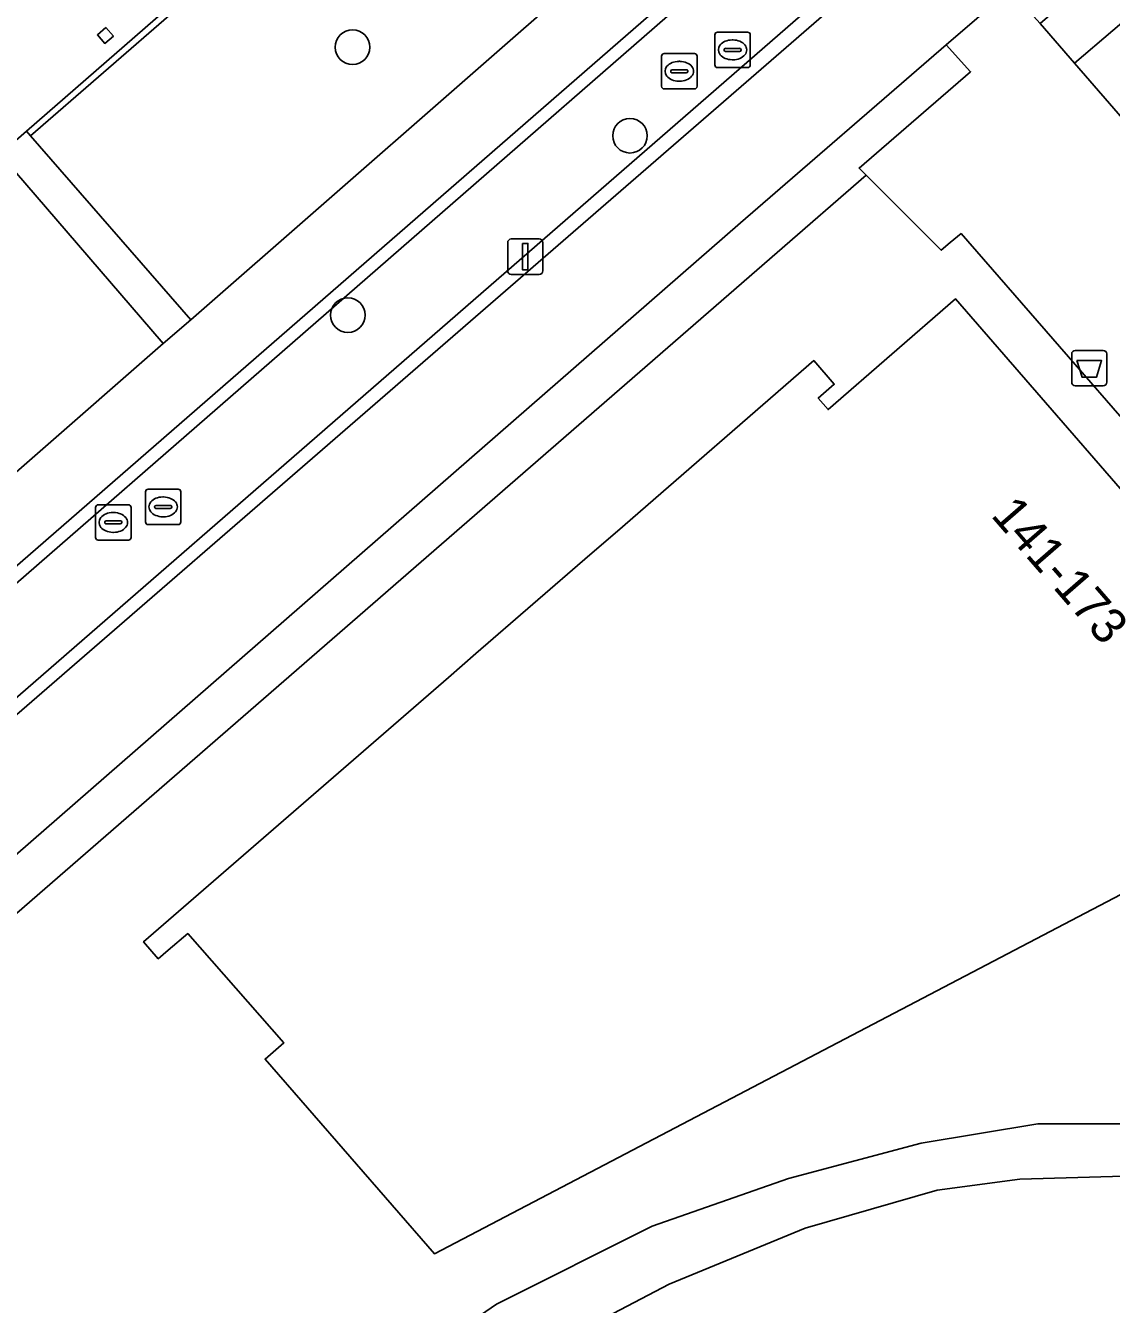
# Model space of a CAD drawing. Extents: x 155887 to 156869, y 383880 to 384678.
# Drawn here: x 156245.28 to 156275.97, y 384049.47 to 384085.6 of the extents above; entities that cross this region are included whole.
import ezdxf

# ---------------------------------------------------------------- set-up
doc = ezdxf.new("R2010")
doc.units = 0
for name, color, linetype in [('IMGEO_Afvalbak', 7, 'Continuous'), ('IMGEO_Berm_groen', 7, 'Continuous'), ('IMGEO_Boom', 7, 'Continuous'), ('IMGEO_Erf', 7, 'Continuous'), ('IMGEO_Fietspad_gesloten', 7, 'Continuous'), ('IMGEO_Greppel_droge_sloot', 7, 'Continuous'), ('IMGEO_Groenvoorziening', 7, 'Continuous'), ('IMGEO_Haag', 7, 'Continuous'), ('IMGEO_Kolk', 7, 'Continuous'), ('IMGEO_Lichtmast', 7, 'Continuous'), ('IMGEO_Pand', 7, 'Continuous'), ('IMGEO_Pand_nummerreeks', 7, 'Continuous'), ('IMGEO_Voetpad_gesloten', 7, 'Continuous'), ('IMGEO_Voetpad_open', 7, 'Continuous')]:
    doc.layers.add(name, color=color, linetype=linetype)

msp = doc.modelspace()

# ---------------------------------------------------------------- linework, layer by layer
at = {"layer": 'IMGEO_Afvalbak'}
for p, q in [((156274.942, 384076.424), (156275.732, 384076.424)), ((156275.732, 384076.424), (156274.942, 384076.424)), ((156274.842, 384075.524), (156274.842, 384076.324)), ((156274.842, 384076.324), (156274.842, 384075.524)), ((156275.832, 384076.324), (156275.832, 384075.524)), ((156275.832, 384075.524), (156275.832, 384076.324)), ((156275.732, 384075.424), (156274.942, 384075.424)), ((156274.942, 384075.424), (156275.732, 384075.424))]:
    msp.add_line(p, q, dxfattribs=at)
msp.add_lwpolyline([(156274.985, 384076.138), (156275.689, 384076.138), (156275.54, 384075.668), (156275.134, 384075.668), (156274.985, 384076.138)], dxfattribs=at)
for centre, start, end in [((156274.942, 384076.324), 90, 180), ((156274.942, 384076.324), 90, 180), ((156275.732, 384076.324), 0, 90), ((156275.732, 384076.324), 360, 90), ((156274.942, 384075.524), 180, 270), ((156274.942, 384075.524), 180, 270), ((156275.732, 384075.524), 270, 0), ((156275.732, 384075.524), 270, 0)]:
    msp.add_arc(centre, 0.1, start, end, dxfattribs=at)
at = {"layer": 'IMGEO_Berm_groen'}
for points in [[(156267.782, 384090.109), (156262.74, 384085.745), (156228.231, 384055.73), (156230.294, 384053.373), (156269.896, 384087.691)], [(156277.086, 384086.398), (156274.92, 384084.542), (156304.211, 384050.794), (156306.425, 384052.676)]]:
    msp.add_lwpolyline(points, close=True, dxfattribs=at)
for points in [[(156229.652, 384056.467), (156266.709, 384088.74)], [(156268.552, 384087.083), (156231.611, 384054.962)]]:
    msp.add_lwpolyline(points, dxfattribs=at)
at = {"layer": 'IMGEO_Boom'}
for centre in [(156254.52, 384084.99), (156262.36, 384082.49), (156254.388, 384077.422)]:
    msp.add_circle(centre, 0.489, dxfattribs=at)
at = {"layer": 'IMGEO_Erf'}
for points in [[(156233.788, 384073.174), (156236.052, 384075.143), (156235.843, 384075.385), (156236.084, 384075.595), (156236.293, 384075.353), (156236.363, 384075.42), (156236.657, 384075.088), (156237.409, 384075.743), (156244.556, 384081.969), (156245.305, 384082.622), (156261.783, 384096.974), (156257.057, 384102.381), (156253.783, 384106.157), (156249.606, 384110.968), (156241.618, 384120.183), (156237.428, 384125.007), (156235.411, 384127.346), (156228.952, 384134.784), (156195.288, 384105.561), (156189.338, 384100.396), (156193.713, 384095.326), (156201.684, 384086.153), (156205.864, 384081.345), (156221.93, 384062.847)], [(156247.552, 384085.548), (156247.761, 384085.306), (156247.519, 384085.096), (156247.31, 384085.338)]]:
    msp.add_lwpolyline(points, close=True, dxfattribs=at)
for points in [[(156276.904, 384073.775), (156271.716, 384079.723), (156271.41, 384079.469), (156271.154, 384079.254), (156269.034, 384081.375), (156170.141, 383995.483)], [(156278.03, 384061.999), (156256.833, 384050.902), (156252.05, 384056.404), (156252.576, 384056.861), (156249.864, 384059.949), (156249.309, 384059.476), (156249.027, 384059.236), (156248.615, 384059.719), (156257.228, 384067.188), (156258.004, 384067.858), (156261.223, 384070.65), (156262.005, 384071.319), (156267.555, 384076.135), (156268.131, 384075.47), (156267.678, 384075.077), (156267.96, 384074.752), (156271.563, 384077.878), (156276.399, 384072.304)], [(156253.789, 384046.184), (156258.588, 384049.482), (156262.988, 384051.68), (156266.837, 384053.029), (156270.587, 384054.028), (156273.886, 384054.577), (156276.336, 384054.577), (156276.642, 384054.607), (156276.789, 384053.144), (156276.326, 384053.098), (156273.378, 384053.011), (156271.04, 384052.699), (156267.307, 384051.623), (156263.463, 384050.043), (156260.322, 384048.399)]]:
    msp.add_lwpolyline(points, dxfattribs=at)
at = {"layer": 'IMGEO_Fietspad_gesloten'}
for points in [[(156321.213, 384132.469), (156314.047, 384125.913), (156291.359, 384106.231), (156284.254, 384100.056), (156283.954, 384099.797), (156269.896, 384087.691), (156230.294, 384053.373), (156228.715, 384051.972), (156223.252, 384047.246), (156221.532, 384045.745), (156182.003, 384011.384), (156180.455, 384010.006), (156174.916, 384005.204), (156173.353, 384003.808), (156169.034, 384000), (156168.573, 383999.541)], [(156225.091, 384044.821), (156232.142, 384050.972), (156265.486, 384080.026), (156271.299, 384085.055), (156273.092, 384086.615), (156283.541, 384095.347), (156286.027, 384097.441), (156286.341, 384097.706), (156304.975, 384114.033), (156305.378, 384113.591), (156305.662, 384113.279), (156306.714, 384114.217), (156306.4, 384114.594), (156306.05, 384115.013), (156315.997, 384123.54), (156323.254, 384130.15), (156323.467, 384130.447)]]:
    msp.add_lwpolyline(points, dxfattribs=at)
at = {"layer": 'IMGEO_Greppel_droge_sloot'}
for points in [[(156266.709, 384088.74), (156229.652, 384056.467)], [(156231.611, 384054.962), (156268.552, 384087.083)]]:
    msp.add_lwpolyline(points, dxfattribs=at)
at = {"layer": 'IMGEO_Groenvoorziening'}
for points in [[(156245.422, 384082.489), (156261.927, 384096.809), (156261.783, 384096.974), (156245.305, 384082.622)], [(156249.95, 384077.285), (156261.303, 384087.219), (156266.381, 384091.712), (156261.927, 384096.809), (156245.422, 384082.489)], [(156241.981, 384070.342), (156249.17, 384076.616), (156244.674, 384081.832), (156237.512, 384075.621)]]:
    msp.add_lwpolyline(points, close=True, dxfattribs=at)
msp.add_lwpolyline([(156167.661, 383993.99), (156169.903, 383993.69), (156170.141, 383995.483), (156269.034, 384081.375), (156268.833, 384081.577), (156271.983, 384084.296), (156271.299, 384085.055), (156265.486, 384080.026), (156232.142, 384050.972), (156225.091, 384044.821), (156184.035, 384009.147), (156173.703, 384000), (156171.742, 383998.278)], dxfattribs=at)
at = {"layer": 'IMGEO_Haag'}
msp.add_lwpolyline([(156245.422, 384082.489), (156261.927, 384096.809), (156261.783, 384096.974), (156245.305, 384082.622)], close=True, dxfattribs=at)
msp.add_lwpolyline([(156167.661, 383993.99), (156169.903, 383993.69), (156170.141, 383995.483), (156269.034, 384081.375), (156268.833, 384081.577), (156271.983, 384084.296), (156271.299, 384085.055), (156265.486, 384080.026), (156232.142, 384050.972), (156225.091, 384044.821), (156184.035, 384009.147), (156173.703, 384000), (156171.742, 383998.278)], dxfattribs=at)
at = {"layer": 'IMGEO_Kolk'}
for p, q in [((156264.758, 384084.489), (156264.758, 384085.341)), ((156264.833, 384085.415), (156265.685, 384085.415)), ((156265.246, 384085.195), (156265.271, 384085.195)), ((156265.759, 384085.341), (156265.759, 384084.489)), ((156263.253, 384083.885), (156263.253, 384084.737)), ((156263.328, 384084.811), (156264.18, 384084.811)), ((156264.254, 384084.737), (156264.254, 384083.885)), ((156265.017, 384084.909), (156265.017, 384084.921)), ((156265.455, 384084.872), (156265.057, 384084.872)), ((156265.06, 384084.958), (156265.458, 384084.958)), ((156265.501, 384084.921), (156265.501, 384084.909)), ((156263.555, 384084.354), (156263.953, 384084.354)), ((156263.741, 384084.591), (156263.766, 384084.591)), ((156265.685, 384084.415), (156264.833, 384084.415)), ((156265.269, 384084.635), (156265.244, 384084.635)), ((156263.512, 384084.305), (156263.512, 384084.317)), ((156263.95, 384084.268), (156263.552, 384084.268)), ((156263.764, 384084.031), (156263.739, 384084.031)), ((156263.996, 384084.317), (156263.996, 384084.305)), ((156264.18, 384083.811), (156263.328, 384083.811)), ((156248.667, 384071.578), (156248.667, 384072.43)), ((156248.742, 384072.504), (156249.594, 384072.504)), ((156249.668, 384072.43), (156249.668, 384071.578)), ((156247.333, 384072.064), (156248.185, 384072.064)), ((156249.155, 384072.284), (156249.18, 384072.284)), ((156247.258, 384071.138), (156247.258, 384071.99)), ((156247.746, 384071.844), (156247.771, 384071.844)), ((156248.259, 384071.99), (156248.259, 384071.138)), ((156248.926, 384071.998), (156248.926, 384072.01)), ((156249.364, 384071.961), (156248.966, 384071.961)), ((156248.969, 384072.047), (156249.367, 384072.047)), ((156249.178, 384071.724), (156249.153, 384071.724)), ((156249.41, 384072.01), (156249.41, 384071.998)), ((156247.517, 384071.558), (156247.517, 384071.57)), ((156247.955, 384071.521), (156247.557, 384071.521)), ((156247.56, 384071.607), (156247.958, 384071.607)), ((156248.001, 384071.57), (156248.001, 384071.558)), ((156249.594, 384071.504), (156248.742, 384071.504)), ((156248.185, 384071.064), (156247.333, 384071.064)), ((156247.769, 384071.284), (156247.744, 384071.284))]:
    msp.add_line(p, q, dxfattribs=at)
for points in [[(156264.758, 384084.489), (156264.758, 384085.341)], [(156264.833, 384085.415), (156265.685, 384085.415)], [(156265.759, 384085.341), (156265.759, 384084.489)], [(156263.253, 384083.885), (156263.253, 384084.737)], [(156263.328, 384084.811), (156264.18, 384084.811)], [(156264.254, 384084.737), (156264.254, 384083.885)], [(156265.685, 384084.415), (156264.833, 384084.415)], [(156264.18, 384083.811), (156263.328, 384083.811)], [(156248.667, 384071.578), (156248.667, 384072.43)], [(156248.742, 384072.504), (156249.594, 384072.504)], [(156249.668, 384072.43), (156249.668, 384071.578)], [(156247.333, 384072.064), (156248.185, 384072.064)], [(156247.258, 384071.138), (156247.258, 384071.99)], [(156248.259, 384071.99), (156248.259, 384071.138)], [(156249.594, 384071.504), (156248.742, 384071.504)], [(156248.185, 384071.064), (156247.333, 384071.064)]]:
    msp.add_lwpolyline(points, dxfattribs=at)
for centre, radius, start, end in [((156264.835, 384085.339), 0.0765, 91.552, 178.448), ((156264.835, 384085.339), 0.0765, 91.552, 178.448), ((156265.683, 384085.339), 0.0765, 1.552, 88.448), ((156265.683, 384085.339), 0.0765, 1.552, 88.448), ((156263.33, 384084.735), 0.0765, 91.552, 178.448), ((156263.33, 384084.735), 0.0765, 91.552, 178.448), ((156264.178, 384084.735), 0.0765, 1.552, 88.448), ((156264.178, 384084.735), 0.0765, 1.552, 88.448), ((156265.057, 384084.918), 0.0403, 85.8775, 175.7526), ((156265.054, 384084.908), 0.0366, 178.938, 274.7102), ((156265.458, 384084.915), 0.043, 264.8664, 352.4533), ((156265.462, 384084.92), 0.0386, 1.7309, 96.639), ((156263.552, 384084.314), 0.0403, 85.8775, 175.7526), ((156263.957, 384084.316), 0.0386, 1.7309, 96.639), ((156264.835, 384084.491), 0.0765, 181.552, 268.448), ((156264.835, 384084.491), 0.0765, 181.552, 268.448), ((156265.683, 384084.491), 0.0765, 271.552, 358.448), ((156265.683, 384084.491), 0.0765, 271.552, 358.448), ((156263.549, 384084.304), 0.0366, 178.938, 274.7102), ((156263.953, 384084.311), 0.043, 264.8664, 352.4533), ((156263.33, 384083.887), 0.0765, 181.552, 268.448), ((156263.33, 384083.887), 0.0765, 181.552, 268.448), ((156264.178, 384083.887), 0.0765, 271.552, 358.448), ((156264.178, 384083.887), 0.0765, 271.552, 358.448), ((156248.744, 384072.428), 0.0765, 91.552, 178.448), ((156248.744, 384072.428), 0.0765, 91.552, 178.448), ((156249.592, 384072.428), 0.0765, 1.552, 88.448), ((156249.592, 384072.428), 0.0765, 1.552, 88.448), ((156247.335, 384071.988), 0.0765, 91.552, 178.448), ((156247.335, 384071.988), 0.0765, 91.552, 178.448), ((156248.183, 384071.988), 0.0765, 1.552, 88.448), ((156248.183, 384071.988), 0.0765, 1.552, 88.448), ((156248.966, 384072.007), 0.0403, 85.8775, 175.7526), ((156248.963, 384071.997), 0.0366, 178.938, 274.7102), ((156249.367, 384072.004), 0.043, 264.8664, 352.4533), ((156249.371, 384072.009), 0.0386, 1.7309, 96.639), ((156247.557, 384071.567), 0.0403, 85.8775, 175.7526), ((156247.554, 384071.557), 0.0366, 178.938, 274.7102), ((156247.958, 384071.564), 0.043, 264.8664, 352.4533), ((156247.962, 384071.569), 0.0386, 1.7309, 96.639), ((156248.744, 384071.58), 0.0765, 181.552, 268.448), ((156248.744, 384071.58), 0.0765, 181.552, 268.448), ((156249.592, 384071.58), 0.0765, 271.552, 358.448), ((156249.592, 384071.58), 0.0765, 271.552, 358.448), ((156247.335, 384071.14), 0.0765, 181.552, 268.448), ((156247.335, 384071.14), 0.0765, 181.552, 268.448), ((156248.183, 384071.14), 0.0765, 271.552, 358.448), ((156248.183, 384071.14), 0.0765, 271.552, 358.448)]:
    msp.add_arc(centre, radius, start, end, dxfattribs=at)
for centre, major_axis, ratio, start_param, end_param in [((156265.245, 384084.915), (-0.387, 0.002), 0.722429, 4.712389, 7.853982), ((156265.27, 384084.915), (-0.39, 0.002), 0.717154, 1.570796, 4.712389), ((156263.74, 384084.311), (-0.387, 0.002), 0.722429, 4.712389, 7.853982), ((156263.765, 384084.311), (-0.39, 0.002), 0.717154, 1.570796, 4.712389), ((156249.154, 384072.004), (-0.387, 0.002), 0.722429, 4.712389, 7.853982), ((156249.179, 384072.004), (-0.39, 0.002), 0.717154, 1.570796, 4.712389), ((156247.745, 384071.564), (-0.387, 0.002), 0.722429, 4.712389, 7.853982), ((156247.77, 384071.564), (-0.39, 0.002), 0.717154, 1.570796, 4.712389)]:
    msp.add_ellipse(centre, major_axis=major_axis, ratio=ratio, start_param=start_param, end_param=end_param, dxfattribs=at)
at = {"layer": 'IMGEO_Lichtmast'}
for p, q in [((156258.904, 384078.672), (156258.904, 384079.472)), ((156258.904, 384079.472), (156258.904, 384078.672)), ((156259.004, 384079.572), (156259.794, 384079.572)), ((156259.794, 384079.572), (156259.004, 384079.572)), ((156259.894, 384079.472), (156259.894, 384078.672)), ((156259.894, 384078.672), (156259.894, 384079.472)), ((156259.794, 384078.572), (156259.004, 384078.572)), ((156259.004, 384078.572), (156259.794, 384078.572))]:
    msp.add_line(p, q, dxfattribs=at)
msp.add_lwpolyline([(156259.324, 384079.447), (156259.474, 384079.447), (156259.474, 384078.697), (156259.324, 384078.697), (156259.324, 384079.447)], dxfattribs=at)
for centre, start, end in [((156259.004, 384079.472), 90, 180), ((156259.004, 384079.472), 90, 180), ((156259.794, 384079.472), 0, 90), ((156259.794, 384079.472), 360, 90), ((156259.004, 384078.672), 180, 270), ((156259.004, 384078.672), 180, 270), ((156259.794, 384078.672), 270, 0), ((156259.794, 384078.672), 270, 0)]:
    msp.add_arc(centre, 0.1, start, end, dxfattribs=at)
at = {"layer": 'IMGEO_Pand'}
msp.add_lwpolyline([(156247.552, 384085.548), (156247.31, 384085.338), (156247.519, 384085.096), (156247.761, 384085.306)], close=True, dxfattribs=at)
msp.add_lwpolyline([(156276.399, 384072.304), (156271.563, 384077.878), (156267.96, 384074.752), (156267.678, 384075.077), (156268.131, 384075.47), (156267.555, 384076.135), (156262.005, 384071.319), (156261.223, 384070.65), (156258.004, 384067.858), (156257.228, 384067.188), (156248.615, 384059.719), (156249.027, 384059.236), (156249.309, 384059.476), (156249.864, 384059.949), (156252.576, 384056.861), (156252.05, 384056.404), (156256.833, 384050.902), (156278.03, 384061.999)], dxfattribs=at)
at = {"layer": 'IMGEO_Voetpad_gesloten'}
msp.add_lwpolyline([(156260.322, 384048.399), (156263.463, 384050.043), (156267.307, 384051.623), (156271.04, 384052.699), (156273.378, 384053.011), (156276.326, 384053.098), (156276.789, 384053.144), (156276.642, 384054.607), (156276.336, 384054.577), (156273.886, 384054.577), (156270.587, 384054.028), (156266.837, 384053.029), (156262.988, 384051.68), (156258.588, 384049.482), (156253.789, 384046.184)], dxfattribs=at)
at = {"layer": 'IMGEO_Voetpad_open'}
for points in [[(156221.196, 384049.632), (156226.604, 384054.357), (156228.715, 384051.972), (156230.294, 384053.373), (156228.231, 384055.73), (156262.74, 384085.745), (156267.782, 384090.109), (156266.381, 384091.712), (156261.303, 384087.219), (156249.95, 384077.285), (156249.17, 384076.616), (156241.981, 384070.342), (156241.203, 384069.676), (156226.832, 384057.225), (156225.312, 384055.892), (156219.734, 384051.063)], [(156307.48, 384046.967), (156304.211, 384050.794), (156274.92, 384084.542), (156273.953, 384085.664), (156273.092, 384086.615), (156271.299, 384085.055), (156271.983, 384084.296), (156268.833, 384081.577), (156269.034, 384081.375), (156271.154, 384079.254), (156271.41, 384079.469), (156271.716, 384079.723), (156276.904, 384073.775), (156277.17, 384073.469), (156279.774, 384075.773), (156291.285, 384062.581), (156288.058, 384059.795), (156291.525, 384055.794), (156292.746, 384054.384), (156299.309, 384046.811)]]:
    msp.add_lwpolyline(points, dxfattribs=at)
for points in [[(156302.817, 384058.029), (156285.623, 384077.838), (156276.712, 384088.043), (156273.953, 384085.664), (156274.92, 384084.542), (156277.086, 384086.398), (156306.425, 384052.676), (156306.981, 384053.222)], [(156245.305, 384082.622), (156244.556, 384081.969), (156244.674, 384081.832), (156249.17, 384076.616), (156249.95, 384077.285), (156245.422, 384082.489)]]:
    msp.add_lwpolyline(points, close=True, dxfattribs=at)

# ---------------------------------------------------------------- texts
at = {"layer": 'IMGEO_Pand_nummerreeks'}
msp.add_text('141-173', height=1, rotation=310.948, dxfattribs=at).set_placement((156272.535, 384071.754))

doc.saveas('drawing.dxf')
